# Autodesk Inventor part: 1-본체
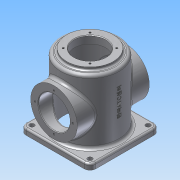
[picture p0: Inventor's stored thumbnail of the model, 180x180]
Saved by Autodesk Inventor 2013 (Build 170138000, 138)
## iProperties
Created: 2015-10
Part Number: 1-본체
Material: 알루미늄 6061
Document SubType Name: Modeling
Designer: Administrator
Density: 2.71 g/cm^3
Mass: 987.172 g
Surface Area: 1038.31 cm^2
Volume: 364.27 cm^3
Author: Administrator
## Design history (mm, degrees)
sketch "스케치1"
  geometry: L1 (0, 0)-(50, 0); L2 (50, 0)-(50, 110); L3 (50, 110)-(0, 110); L4 (0, 110)-(0, 0)
  constraints: 8 end point, 2 parallel, 1 horizontal, 1 perpendicular
  dimensions: "d0" = 110 distance of L3.end L1.start; "d1" = 100 diameter of L2 L4
revolve "회전1" sketch "스케치1" stored, may be unused: angle "d2" = 90 deg
sketch "스케치2"
  geometry: C1 r 40 at (0, 0); 1 further point
  constraints: 1 centre point, 1 coincident
  dimensions: "d3" = 80 diameter of C1
extrude "돌출1" join sketch "스케치2" distance "d5" = 5; taper "d6" = 0 deg
sketch "스케치3"
  geometry: L1 (-60, 60)-(60, 60); L2 (60, 60)-(60, -60); L3 (60, -60)-(-60, -60); L4 (-60, -60)-(-60, 60); 3 further points
  constraints: 8 end point, 2 midpoint, 2 parallel, 1 horizontal, 1 horizontal alignment, 1 perpendicular, 1 vertical alignment
  dimensions: "d7" = 120 distance of L1.start L1.end; "d9" = 120 distance of L1.end L2.end
extrude "돌출2" join sketch "스케치3" distance "d10" = 10; taper "d11" = 0 deg
sketch "스케치4"
  geometry: L1 (-60, -10)-(60, -10) reference; C1 r 40 at (0, 50); 1 further point
  constraints: 1 centre point, 1 vertical alignment
  dimensions: "d12" = 60 distance from line of L1 C1.centre; "d13" = 80 diameter of C1
extrude "돌출3" join sketch "스케치4" stored distance "d14" = 124; taper "d15" = 0 deg
hole "구멍1" diameter "d18" = 54; stored, may be unused: countersink angle "d22" = 90 deg, drill point angle "d24" = 118 deg; dims "d16" = 10, "d17" = 10, "d19" = 6, "d20" = 90, "d21" = 112, "d23" = 8
hole "구멍2" diameter "d27" = 54; stored, may be unused: countersink angle "d31" = 90 deg, drill point angle "d33" = 118 deg; dims "d25" = 10, "d26" = 10, "d28" = 6, "d29" = 90, "d30" = 112, "d32" = 8
sketch "스케치5"
  geometry: A1 r 32.5 centre (0, 0) between (-22.981, 22.981) and (22.981, 22.981); 3 further points
  constraints: 4 point on circle, 2 vertical alignment, 1 centre point, 1 coincident, 1 horizontal alignment
  dimensions: "d34" = 65 diameter of A1; "d37" = 90 deg dimension on point (0, 0) A1.end A1.start
hole "구멍3" sketch "스케치5" at (-22.981, 22.981), (22.981, 22.981), (-22.981, -22.981), (22.981, -22.981) diameter "d39" = 3.242; stored, may be unused: countersink angle "d43" = 90 deg, drill point angle "d45" = 118 deg; dims "d40" = 8, "d41" = 90, "d42" = 112, "d44" = 10
sketch "스케치6"
  geometry: C1 r 27 at (0, 0) reference; 2 further points
  constraints: 1 vertical alignment
  dimensions: "d46" = 32.5 distance of C1.centre point (0, 32.5)
hole "구멍4" sketch "스케치6" at (0, 32.5) diameter "d47" = 3.242; stored, may be unused: countersink angle "d51" = 90 deg, drill point angle "d53" = 118 deg; dims "d48" = 8, "d49" = 90, "d50" = 112, "d52" = 10
fillet "모깎기1" dims "d57" = 10
sketch "스케치7"
  geometry: 5 further points
  constraints: 2 horizontal alignment, 2 vertical alignment
  dimensions: "d58" = 50 horizontal distance of point (0, 0) point (-50, 50); "d59" = 50 horizontal distance of point (0, 0) point (-50, 50); "d60" = 50 horizontal distance of point (50, 50) point (0, 0); "d61" = 50 horizontal distance of point (0, 0) point (-50, -50)
hole "구멍5" sketch "스케치7" at (-50, 50), (50, 50), (50, -50), (-50, -50) diameter "d62" = 8; stored, may be unused: countersink angle "d66" = 90 deg, drill point angle "d68" = 118 deg; dims "d63" = 8, "d64" = 90, "d65" = 112, "d67" = 10
chamfer "모따기1" distance "d69" = 3; stored, may be unused: second distance "d70" = 2, angle "d71" = 45 deg
chamfer "모따기2" distance "d72" = 1; stored, may be unused: second distance "d73" = 2, angle "d74" = 45 deg
fillet "모깎기2" dims "d75" = 5
fillet "모깎기3" dims "d76" = 5
fillet "모깎기4" dims "d77" = 3
chamfer "모따기3" distance "d78" = 1; stored, may be unused: second distance "d79" = 2, angle "d80" = 45 deg
fillet "모깎기5" dims "d81" = 3
fillet "모깎기6" dims "d82" = 3
node "작업 평면1"
sketch "스케치9"
  geometry: L1 (-19.887, 3.602)-(29.887, 3.602); L2 (29.887, 3.602)-(29.887, -3.602); L3 (29.887, -3.602)-(-19.887, -3.602); L4 (-19.887, -3.602)-(-19.887, 3.602); L5 (-65, 48)-(-65, -48) reference; 4 further points
  constraints: 2 horizontal alignment, 2 midpoint, 1 vertical alignment, 2 other
  dimensions: "d83" = 70 distance from line of point (5, 0) L5
feature "엠보싱1" sketch "스케치9" dims "d0" = 110, "d1" = 100, "d84" = 0.5, "d85" = 0
node "솔리드1"
pattern_circular "원형 패턴1" dims angle "d55" = 360 deg
mirror "대칭1"
